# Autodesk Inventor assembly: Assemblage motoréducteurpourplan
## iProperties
Shininess: 64.0
Length Units: 11269
Angle Units: 11279
Time Units: 11290
Mass Units: 11283
Length Display Precision: 3
Angle Display Precision: 2
Compacted: True
Created: 2004-09
Part Number: Assemblage motoréducteurpourplan
Document SubType Name: Assembly
Designer: Laurent
Density: 0.0
Volumn: 0.0
Area: 0.0
PropertySet Name: Model Information
Control State: 0
Master: False
Checked Out: False
Author: Laurent
